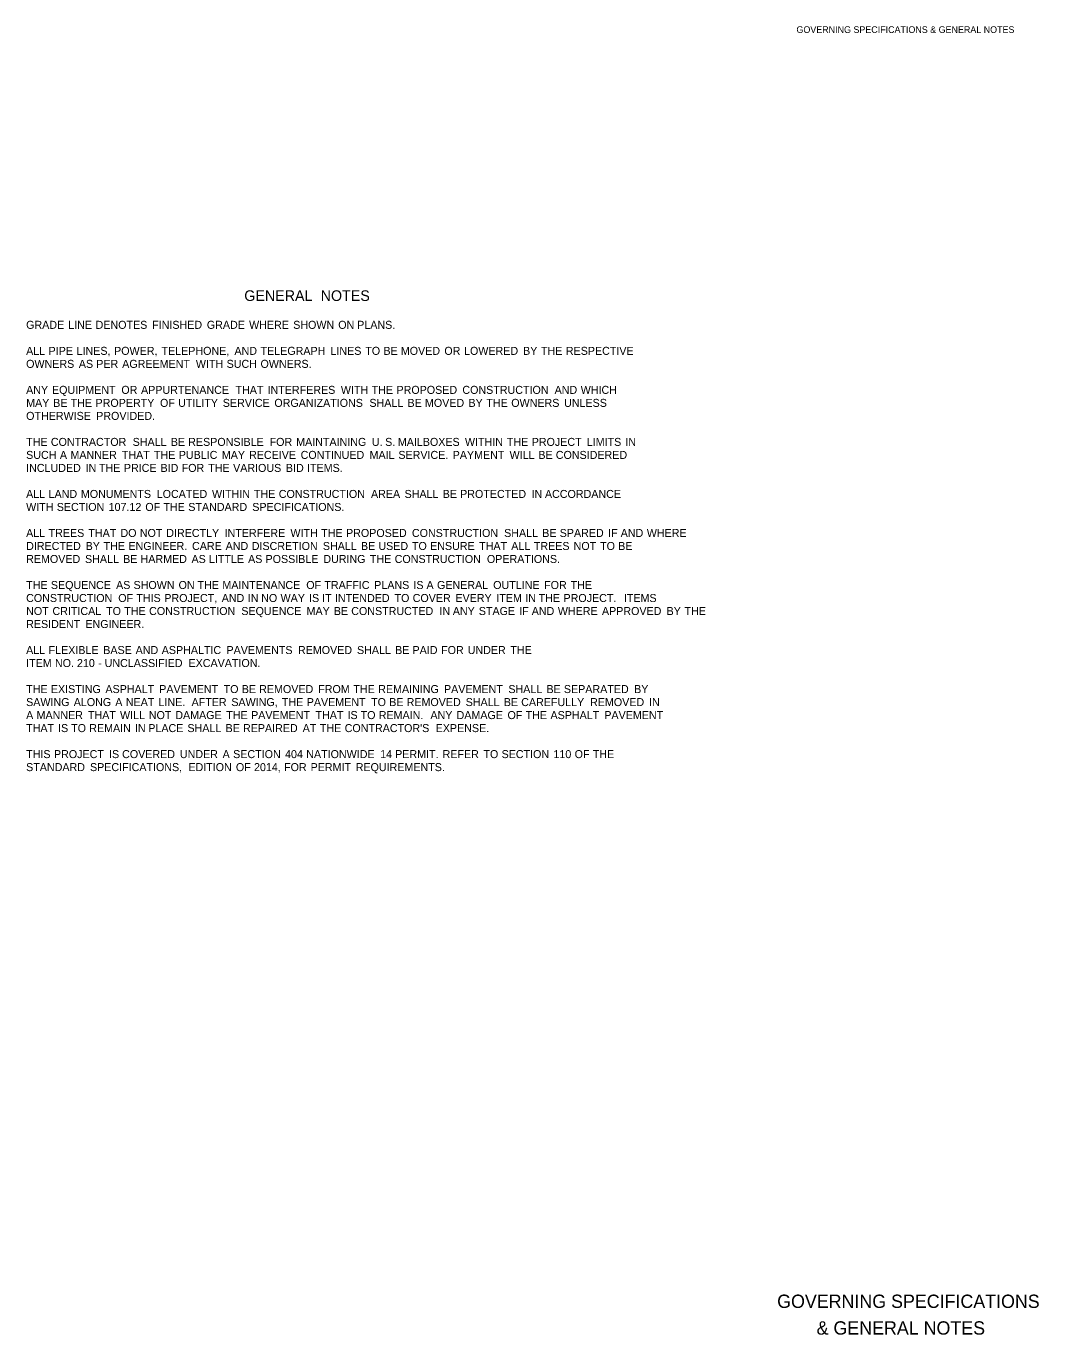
# Model space of a CAD drawing. Extents: x 178 to 1654, y 36 to 1017.
# Drawn here: x 894 to 1654, y 36 to 1017 of the extents above; entities that cross this region are included whole.
import ezdxf

# ---------------------------------------------------------------- set-up
doc = ezdxf.new("R2010")
doc.units = 0
doc.layers.add('Default', color=7, linetype='Continuous')

msp = doc.modelspace()

# ---------------------------------------------------------------- texts
at = {"layer": 'Default'}
for s, height, p in [('GOVERNING SPECIFICATIONS & GENERAL NOTES', 5, (1472.12, 1011.67)), ('GENERAL', 8, (1057.95, 810.77)), (' NOTES', 8, (1112.28, 810.77)), ('GRADE', 6, (894.32, 789.89)), (' LINE', 6, (923.68, 789.89)), (' DENOTES', 6, (944.2, 789.89)), (' FINISHED', 6, (986.62, 789.89)), (' GRADE', 6, (1027.63, 789.89)), (' WHERE', 6, (1059.32, 789.89)), (' SHOWN', 6, (1092.41, 789.89)), (' ON', 6, (1126.19, 789.89)), (' PLANS.', 6, (1140.41, 789.89)), ('ALL', 6, (894.32, 770.39)), (' PIPE', 6, (908.93, 770.39)), (' LINES,', 6, (929.92, 770.39)), (' POWER,', 6, (958.06, 770.39)), (' TELEPHONE,', 6, (993.64, 770.39)), (' AND', 6, (1048.34, 770.39)), (' TELEGRAPH', 6, (1067.92, 770.39)), (' LINES', 6, (1120.35, 770.39)), (' TO', 6, (1146.47, 770.39)), (' BE', 6, (1160.07, 770.39)), (' MOVED', 6, (1173.13, 770.39)), (' OR', 6, (1205.76, 770.39)), (' LOWERED', 6, (1220.55, 770.39)), (' BY', 6, (1264.82, 770.39)), (' THE', 6, (1278.27, 770.39)), (' RESPECTIVE', 6, (1296.91, 770.39)), ('OWNERS', 6, (894.32, 760.64)), (' AS', 6, (931.61, 760.64)), (' PER', 6, (944.68, 760.64)), (' AGREEMENT', 6, (964.13, 760.64)), (' WITH', 6, (1019.4, 760.64)), (' SUCH', 6, (1042.47, 760.64)), (' OWNERS.', 6, (1067.88, 760.64)), ('ANY', 6, (894.32, 741.14)), (' EQUIPMENT', 6, (911.49, 741.14)), (' OR', 6, (963.49, 741.14)), (' APPURTENANCE', 6, (978.28, 741.14)), (' THAT', 6, (1049.12, 741.14)), (' INTERFERES', 6, (1073.17, 741.14)), (' WITH', 6, (1128.16, 741.14)), (' THE', 6, (1151.23, 741.14)), (' PROPOSED', 6, (1169.88, 741.14)), (' CONSTRUCTION', 6, (1219.29, 741.14)), (' AND', 6, (1288.46, 741.14)), (' WHICH', 6, (1308.05, 741.14)), ('MAY', 6, (894.32, 731.39)), (' BE', 6, (912.42, 731.39)), (' THE', 6, (925.49, 731.39)), (' PROPERTY', 6, (944.14, 731.39)), (' OF', 6, (992.52, 731.39)), (' UTILITY', 6, (1006.11, 731.39)), (' SERVICE', 6, (1039.58, 731.39)), (' ORGANIZATIONS', 6, (1078.27, 731.39)), (' SHALL', 6, (1149.57, 731.39)), (' BE', 6, (1178.16, 731.39)), (' MOVED', 6, (1191.22, 731.39)), (' BY', 6, (1223.85, 731.39)), (' THE', 6, (1237.3, 731.39)), (' OWNERS', 6, (1255.95, 731.39)), (' UNLESS', 6, (1295.57, 731.39)), ('OTHERWISE', 6, (894.32, 721.64)), (' PROVIDED.', 6, (944.64, 721.64)), ('THE', 6, (894.32, 702.14)), (' CONTRACTOR', 6, (910.64, 702.14)), (' SHALL', 6, (972, 702.14)), (' BE', 6, (1000.6, 702.14)), (' RESPONSIBLE', 6, (1013.66, 702.14)), (' FOR', 6, (1074.72, 702.14)), (' MAINTAINING', 6, (1094.63, 702.14)), (' U.', 6, (1151.39, 702.14)), (' S.', 6, (1161.37, 702.14)), (' MAILBOXES', 6, (1170.89, 702.14)), (' WITHIN', 6, (1221.23, 702.14)), (' THE', 6, (1252.67, 702.14)), (' PROJECT', 6, (1271.32, 702.14)), (' LIMITS', 6, (1312.61, 702.14)), (' IN', 6, (1341.52, 702.14)), ('SUCH', 6, (894.32, 692.39)), (' A', 6, (917.4, 692.39)), (' MANNER', 6, (925.33, 692.39)), (' THAT', 6, (963.88, 692.39)), (' THE', 6, (987.93, 692.39)), (' PUBLIC', 6, (1006.58, 692.39)), (' MAY', 6, (1038.86, 692.39)), (' RECEIVE', 6, (1059.29, 692.39)), (' CONTINUED', 6, (1097.98, 692.39)), (' MAIL', 6, (1149.7, 692.39)), (' SERVICE.', 6, (1171.29, 692.39)), (' PAYMENT', 6, (1212.02, 692.39)), (' WILL', 6, (1254.71, 692.39)), (' BE', 6, (1276.3, 692.39)), (' CONSIDERED', 6, (1289.37, 692.39)), ('INCLUDED', 6, (894.32, 682.64)), (' IN', 6, (936.72, 682.64)), (' THE', 6, (946.75, 682.64)), (' PRICE', 6, (965.4, 682.64)), (' BID', 6, (992.9, 682.64)), (' FOR', 6, (1008.75, 682.64)), (' THE', 6, (1028.67, 682.64)), (' VARIOUS', 6, (1047.32, 682.64)), (' BID', 6, (1086.94, 682.64)), (' ITEMS.', 6, (1102.8, 682.64)), ('ALL', 6, (894.32, 663.14)), (' LAND', 6, (908.93, 663.14)), (' MONUMENTS', 6, (933.17, 663.14)), (' LOCATED', 6, (990.02, 663.14)), (' WITHIN', 6, (1031.5, 663.14)), (' THE', 6, (1062.94, 663.14)), (' CONSTRUCTION', 6, (1081.59, 663.14)), (' AREA', 6, (1150.77, 663.14)), (' SHALL', 6, (1175.95, 663.14)), (' BE', 6, (1204.54, 663.14)), (' PROTECTED', 6, (1217.6, 663.14)), (' IN', 6, (1271.19, 663.14)), (' ACCORDANCE', 6, (1281.22, 663.14)), ('WITH', 6, (894.32, 653.39)), (' SECTION', 6, (915.06, 653.39)), (' 107.12', 6, (953.96, 653.39)), (' OF', 6, (981.48, 653.39)), (' THE', 6, (995.06, 653.39)), (' STANDARD', 6, (1013.71, 653.39)), (' SPECIFICATIONS.', 6, (1061.71, 653.39)), ('ALL', 6, (894.32, 633.89)), (' TREES', 6, (908.93, 633.89)), (' THAT', 6, (938.78, 633.89)), (' DO', 6, (962.83, 633.89)), (' NOT', 6, (977.36, 633.89)), (' DIRECTLY', 6, (997.21, 633.89)), (' INTERFERE', 6, (1040.94, 633.89)), (' WITH', 6, (1090.33, 633.89)), (' THE', 6, (1113.4, 633.89)), (' PROPOSED', 6, (1132.05, 633.89)), (' CONSTRUCTION', 6, (1181.45, 633.89)), (' SHALL', 6, (1250.63, 633.89)), (' BE', 6, (1279.22, 633.89)), (' SPARED', 6, (1292.29, 633.89)), (' IF', 6, (1328.65, 633.89)), (' AND', 6, (1338.04, 633.89)), (' WHERE', 6, (1357.62, 633.89)), ('DIRECTED', 6, (894.32, 624.14)), (' BY', 6, (936.72, 624.14)), (' THE', 6, (950.17, 624.14)), (' ENGINEER.', 6, (968.82, 624.14)), (' CARE', 6, (1016.54, 624.14)), (' AND', 6, (1041.71, 624.14)), (' DISCRETION', 6, (1061.3, 624.14)), (' SHALL', 6, (1114.64, 624.14)), (' BE', 6, (1143.23, 624.14)), (' USED', 6, (1156.3, 624.14)), (' TO', 6, (1181.47, 624.14)), (' ENSURE', 6, (1195.07, 624.14)), (' THAT', 6, (1231.89, 624.14)), (' ALL', 6, (1255.94, 624.14)), (' TREES', 6, (1272.89, 624.14)), (' NOT', 6, (1302.73, 624.14)), (' TO', 6, (1322.59, 624.14)), (' BE', 6, (1336.18, 624.14)), ('REMOVED', 6, (894.32, 614.39)), (' SHALL', 6, (936.26, 614.39)), (' BE', 6, (964.85, 614.39)), (' HARMED', 6, (977.92, 614.39)), (' AS', 6, (1016.13, 614.39)), (' LITTLE', 6, (1029.21, 614.39)), (' AS', 6, (1058.57, 614.39)), (' POSSIBLE', 6, (1071.65, 614.39)), (' DURING', 6, (1115, 614.39)), (' THE', 6, (1149.87, 614.39)), (' CONSTRUCTION', 6, (1168.52, 614.39)), (' OPERATIONS.', 6, (1237.7, 614.39)), ('THE', 6, (894.32, 594.89)), (' SEQUENCE', 6, (910.64, 594.89)), (' AS', 6, (959.57, 594.89)), (' SHOWN', 6, (972.65, 594.89)), (' ON', 6, (1006.43, 594.89)), (' THE', 6, (1020.65, 594.89)), (' MAINTENANCE', 6, (1039.29, 594.89)), (' OF', 6, (1102.2, 594.89)), (' TRAFFIC', 6, (1115.79, 594.89)), (' PLANS', 6, (1153.18, 594.89)), (' IS', 6, (1182.56, 594.89)), (' A', 6, (1192.37, 594.89)), (' GENERAL', 6, (1200.3, 594.89)), (' OUTLINE', 6, (1242.4, 594.89)), (' FOR', 6, (1280.62, 594.89)), (' THE', 6, (1300.53, 594.89)), ('CONSTRUCTION', 6, (894.32, 585.14)), (' OF', 6, (961.17, 585.14)), (' THIS', 6, (974.75, 585.14)), (' PROJECT,', 6, (995.74, 585.14)), (' AND', 6, (1038.78, 585.14)), (' IN', 6, (1058.36, 585.14)), (' NO', 6, (1068.39, 585.14)), (' WAY', 6, (1082.92, 585.14)), (' IS', 6, (1104.28, 585.14)), (' IT', 6, (1114.09, 585.14)), (' INTENDED', 6, (1123.7, 585.14)), (' TO', 6, (1168.43, 585.14)), (' COVER', 6, (1182.03, 585.14)), (' EVERY', 6, (1214.06, 585.14)), (' ITEM', 6, (1244.75, 585.14)), (' IN', 6, (1266.47, 585.14)), (' THE', 6, (1276.5, 585.14)), (' PROJECT.', 6, (1295.15, 585.14)), ('  ITEMS', 6, (1338.2, 585.14)), ('NOT', 6, (894.32, 575.39)), (' CRITICAL', 6, (911.84, 575.39)), (' TO', 6, (952.07, 575.39)), (' THE', 6, (965.67, 575.39)), (' CONSTRUCTION', 6, (984.32, 575.39)), (' SEQUENCE', 6, (1053.49, 575.39)), (' MAY', 6, (1102.43, 575.39)), (' BE', 6, (1122.86, 575.39)), (' CONSTRUCTED', 6, (1135.93, 575.39)), (' IN', 6, (1202.09, 575.39)), (' ANY', 6, (1212.11, 575.39)), (' STAGE', 6, (1231.62, 575.39)), (' IF', 6, (1261.92, 575.39)), (' AND', 6, (1271.31, 575.39)), (' WHERE', 6, (1290.9, 575.39)), (' APPROVED', 6, (1323.98, 575.39)), (' BY', 6, (1372.46, 575.39)), (' THE', 6, (1385.91, 575.39)), ('RESIDENT', 6, (894.32, 565.64)), (' ENGINEER.', 6, (936.54, 565.64)), ('ALL', 6, (894.32, 546.14)), (' FLEXIBLE', 6, (908.93, 546.14)), (' BASE', 6, (949.95, 546.14)), (' AND', 6, (974.2, 546.14)), (' ASPHALTIC', 6, (993.79, 546.14)), (' PAVEMENTS', 6, (1042.37, 546.14)), (' REMOVED', 6, (1095.98, 546.14)), (' SHALL', 6, (1140.25, 546.14)), (' BE', 6, (1168.84, 546.14)), (' PAID', 6, (1181.91, 546.14)), (' FOR', 6, (1203.36, 546.14)), (' UNDER', 6, (1223.27, 546.14)), (' THE', 6, (1255.29, 546.14)), ('ITEM', 6, (894.32, 536.39)), (' NO.', 6, (913.71, 536.39)), (' 210', 6, (930.21, 536.39)), (' UNCLASSIFIED', 6, (950.97, 536.39)), (' EXCAVATION.', 6, (1013.88, 536.39)), (' -', 6, (946.12, 536.39)), ('THE', 6, (894.32, 516.89)), (' EXISTING', 6, (910.64, 516.89)), (' ASPHALT', 6, (951.57, 516.89)), (' PAVEMENT', 6, (991.94, 516.89)), (' TO', 6, (1040.22, 516.89)), (' BE', 6, (1053.82, 516.89)), (' REMOVED', 6, (1066.88, 516.89)), (' FROM', 6, (1111.16, 516.89)), (' THE', 6, (1137.54, 516.89)), (' REMAINING', 6, (1156.18, 516.89)), (' PAVEMENT', 6, (1205.5, 516.89)), (' SHALL', 6, (1253.78, 516.89)), (' BE', 6, (1282.37, 516.89)), (' SEPARATED', 6, (1295.44, 516.89)), (' BY', 6, (1348.11, 516.89)), ('SAWING', 6, (894.32, 507.14)), (' ALONG', 6, (927.79, 507.14)), (' A', 6, (958.94, 507.14)), (' NEAT', 6, (966.88, 507.14)), (' LINE.', 6, (991.4, 507.14)), ('  AFTER', 6, (1013.96, 507.14)), (' SAWING,', 6, (1045.99, 507.14)), (' THE', 6, (1083.9, 507.14)), (' PAVEMENT', 6, (1102.55, 507.14)), (' TO', 6, (1150.83, 507.14)), (' BE', 6, (1164.43, 507.14)), (' REMOVED', 6, (1177.49, 507.14)), (' SHALL', 6, (1221.76, 507.14)), (' BE', 6, (1250.36, 507.14)), (' CAREFULLY', 6, (1263.42, 507.14)), (' REMOVED', 6, (1315.07, 507.14)), (' IN', 6, (1359.34, 507.14)), ('A', 6, (894.32, 497.39)), (' MANNER', 6, (899.92, 497.39)), (' THAT', 6, (938.47, 497.39)), (' WILL', 6, (962.52, 497.39)), (' NOT', 6, (984.11, 497.39)), (' DAMAGE', 6, (1003.97, 497.39)), (' THE', 6, (1042.18, 497.39)), (' PAVEMENT', 6, (1060.83, 497.39)), (' THAT', 6, (1109.12, 497.39)), (' IS', 6, (1133.17, 497.39)), (' TO', 6, (1142.98, 497.39)), (' REMAIN.', 6, (1156.57, 497.39)), ('  ANY', 6, (1193.1, 497.39)), (' DAMAGE', 6, (1214.94, 497.39)), (' OF', 6, (1253.15, 497.39)), (' THE', 6, (1266.74, 497.39)), (' ASPHALT', 6, (1285.39, 497.39)), (' PAVEMENT', 6, (1325.76, 497.39)), ('THAT', 6, (894.32, 487.64)), (' IS', 6, (916.04, 487.64)), (' TO', 6, (925.85, 487.64)), (' REMAIN', 6, (939.44, 487.64)), (' IN', 6, (973.69, 487.64)), (' PLACE', 6, (983.72, 487.64)), (' SHALL', 6, (1013.09, 487.64)), (' BE', 6, (1041.68, 487.64)), (' REPAIRED', 6, (1054.75, 487.64)), (' AT', 6, (1099.49, 487.64)), (' THE', 6, (1112.36, 487.64)), (" CONTRACTOR'S", 6, (1131.01, 487.64)), (' EXPENSE.', 6, (1199.25, 487.64)), ('THIS', 6, (894.32, 468.14)), (' PROJECT', 6, (912.97, 468.14)), (' IS', 6, (954.27, 468.14)), (' COVERED', 6, (964.07, 468.14)), (' UNDER', 6, (1007.42, 468.14)), (' A', 6, (1039.45, 468.14)), (' SECTION', 6, (1047.38, 468.14)), (' 404', 6, (1086.29, 468.14)), (' NATIONWIDE', 6, (1102.19, 468.14)), (' 14', 6, (1157.63, 468.14)), (' PERMIT.', 6, (1168.87, 468.14)), (' REFER', 6, (1204.47, 468.14)), (' TO', 6, (1235.1, 468.14)), (' SECTION', 6, (1248.7, 468.14)), (' 110', 6, (1287.6, 468.14)), (' OF', 6, (1303.51, 468.14)), (' THE', 6, (1317.1, 468.14)), ('STANDARD', 6, (894.32, 458.39)), (' SPECIFICATIONS,', 6, (939.99, 458.39)), (' EDITION', 6, (1013.78, 458.39)), (' OF', 6, (1049.42, 458.39)), (' 2014,', 6, (1063.01, 458.39)), (' FOR', 6, (1085.56, 458.39)), (' PERMIT', 6, (1105.47, 458.39)), (' REQUIREMENTS.', 6, (1139.3, 458.39)), ('GOVERNING SPECIFICATIONS ', 10, (1457.63, 56.02)), ('& GENERAL NOTES', 10, (1487.23, 36.02))]:
    msp.add_text(s, height=height, dxfattribs=at).set_placement(p)

doc.saveas('drawing.dxf')
